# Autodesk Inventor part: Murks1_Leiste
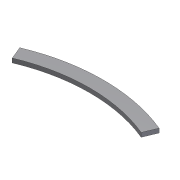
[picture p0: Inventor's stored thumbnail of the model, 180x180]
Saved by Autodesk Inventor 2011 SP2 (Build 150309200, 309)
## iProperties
Created: 2012-07
Part Number: Murks1_Leiste
Document SubType Name: Modeling
Designer: Thomas Kötschau
Density: 1 g/cm^3
Author: Thomas Kötschau
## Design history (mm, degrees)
sketch "Skizze1"
  geometry: L1 (-306.147, 739.104)-(-331.021, 799.156); L2 (306.147, 739.104)-(331.021, 799.156); A1 r 800 centre (0, 0) between (306.147, 739.104) and (-306.147, 739.104); A2 r 865 centre (0, 0) between (331.021, 799.156) and (-331.021, 799.156); 2 further points
  constraints: 5 point on circle, 4 end point, 2 centre point, 2 point on line, 1 coincident, 1 vertical alignment
  dimensions: "d0" = 65 radial gap between concentric circles of A2 A1; "d1" = 800 radius of A1; "d4" = 45 deg angle of L2 L1; "d6" = 865 radius of A2 (derived)
extrude "Extrusion1" new body sketch "Skizze1" distance "d2" = 20; taper "d3" = 0 deg
node "Volumenkörper1"
